Omron CX-Programmer project NewProject (CX-Programmer 2.1)

# PLC NewPLC1: CQM1H CPU51

## Global symbols (name address type ; comment)
PollEnded 200.01 BOOL
PollStatic1 TIM004 BOOL
PollStatic2 TIM005 BOOL
RcvdCmplt 202.00 BOOL
RcvdDrpd 202.01 BOOL
T4_T5Trpd 202.04 BOOL
Tim4_5Chgd 202.02 BOOL

## Program NewProgram1 (no task)
Local symbols
AprchTop 11.00 BOOL
BotSlwDn 0.09 BOOL
BrakeProb1 80.01 BOOL
BrakeProb2 80.02 BOOL
BrkPrRlseTim TIM021 BOOL
BrkSetPB 1.04 BOOL
ByPassON 0.03 BOOL
CarBrake 52.00 BOOL
CarBrkSnsr 52.00 BOOL
Ch3EqlErr 17.00 BOOL
Ch3RngErr 17.01 BOOL
Ch3SnsrlErr 17.00 BOOL  ; Channel 3 is showing a sensor error. Check connections from the temperature module to the thermocouple and also check the thermistor on the module.
Ch60Chgd 70.03 BOOL
Ch60Chgd_ 70.04 BOOL
ChkCarBrkSet TIM151 BOOL
CoolFanMtrOL 1.07 BOOL
CoolFanONDly TIM153 BOOL
DiagDtctd 82.00 BOOL  ; Diagnostic condition has been detected
DiagLtchRst TIM171 BOOL
DiagReset 49.07 BOOL
DiagRstDlay TIM170 BOOL
DnLever 1.03 BOOL
DrmBrkSol 100.02 BOOL
Drum120RPM 0.14 BOOL
DrumDn 1.05 BOOL
DrumMaxSpd TIM159 BOOL
DrumNotDN TIM161 BOOL
DrumNotUP TIM160 BOOL
DrumOvr130RPM 80.06 BOOL
DrumOvrRPM 80.08 BOOL
DrumOvrSpd 0.15 BOOL
DrumOvrSpdTmr TIM157 BOOL
DrumUP 1.06 BOOL
DrumWrongDir 80.09 BOOL
DrvDNPot1 101.02 BOOL
DrvDNPot2 101.03 BOOL
DrvDnCmd1 102.02 BOOL
DrvDnCmd2 102.03 BOOL
DrvUPCmd 102.00 BOOL
DrvUPCmd1 102.00 BOOL
DrvUPCmd2 102.01 BOOL
DrvUPPot1 101.00 BOOL
DrvUPPot2 101.01 BOOL
DwnCntl 99.01 BOOL
EncdrFailBit 80.07 BOOL
EncdrFailTim TIM158 BOOL
FanMtrOL 80.03 BOOL
FloatSw 0.12 BOOL
Flr01Set 11.01 BOOL
Flr02Set 11.02 BOOL
Flr03Set 11.03 BOOL
Flr04Set 11.04 BOOL
Flr05Set 11.05 BOOL
Flr06Set 11.06 BOOL
Flr07Set 11.07 BOOL
Flr08Set 11.08 BOOL
Flr09Set 11.09 BOOL
Flr10Set 11.10 BOOL
Flr11Set 11.11 BOOL
Flr12Set 11.12 BOOL
Flr13Set 11.13 BOOL
Flr14Set 12.01 BOOL
Flr15Set 12.02 BOOL
Flr16Set 12.03 BOOL
Flr17Set 12.04 BOOL
Flr18Set 12.05 BOOL
Flr19Set 12.06 BOOL
Flr20Set 12.07 BOOL
Flr21Set 12.08 BOOL
Flr22Set 12.09 BOOL
Flr23Set 12.10 BOOL
Flr24Set 12.11 BOOL
Flr25Set 12.12 BOOL
Flr26Set 12.13 BOOL
Flr27Set 13.01 BOOL
Flr28Set 13.02 BOOL
Flr29Set 13.03 BOOL
Flr30Set 13.04 BOOL
Flr31Set 13.05 BOOL
Flr32Set 13.06 BOOL
Flr33Set 13.07 BOOL
Flr34Set 13.08 BOOL
Flr356Set 13.10 BOOL
Flr35Set 13.09 BOOL
Flr36Set 13.10 BOOL
Flr37Set 13.11 BOOL
Flr38Set 13.12 BOOL
Flr39Set 13.13 BOOL
Flr40Set 14.01 BOOL
Flr41Set 14.02 BOOL
Flr42Set 14.03 BOOL
Flr43Set 14.04 BOOL
Flr44Set 14.05 BOOL
Flr45Set 14.06 BOOL
Flr46Set 14.07 BOOL
Flr47Set 14.08 BOOL
Flr48Set 14.09 BOOL
Flr49Set 14.10 BOOL
Flr50Set 14.11 BOOL
HiSpLkOut 0.13 BOOL
LdngGates 0.11 BOOL
MainAux 0.00 BOOL
PauseWrite 70.00 BOOL
PollRqst 200.00 BOOL
Prep2Txmt 70.05 BOOL
ResitorA 101.04 BOOL
ResitorB 101.06 BOOL
SSSFault 0.02 BOOL
SSSFaulttMR TIM154 BOOL
SSSNoStart 0.03 BOOL
SafetyLS 52.03 BOOL
SafetyTripped 80.00 BOOL
SafetyTrpd TIM150 BOOL
SetCarBrk 60.00 BOOL
SlkRopeDet 0.10 BOOL
SlowDnCmd 99.03 BOOL
SlowUpCmd 99.02 BOOL
StopMotor 100.01 BOOL
StrUPDly TIM021 BOOL  ; Delays starting the drum in the UP direction until after the drum brake has been released.
StrtDNDly TIM022 BOOL
StrtMotor 100.00 BOOL
StrtWiper 101.05 BOOL
TopSlwDn 0.08 BOOL
TurnFanON 17.03 BOOL
UPCntl 99.00 BOOL
UpLever 1.02 BOOL
VacSetP1 TIM010 BOOL
VacSetP2 TIM011 BOOL
VacShutDN 80.10 BOOL  ; This bit is latched if the vacumm across the oil filter rises too HI
VacShutOFFBit 19.01 BOOL  ; Shutdown the entire machine.
VacTOOHi 19.00 BOOL  ; Change Filter at this point
VacTOOHiBit 19.01 BOOL
ValveShnt 102.04 BOOL
ValveShnt2 102.04 BOOL

### Section Section1

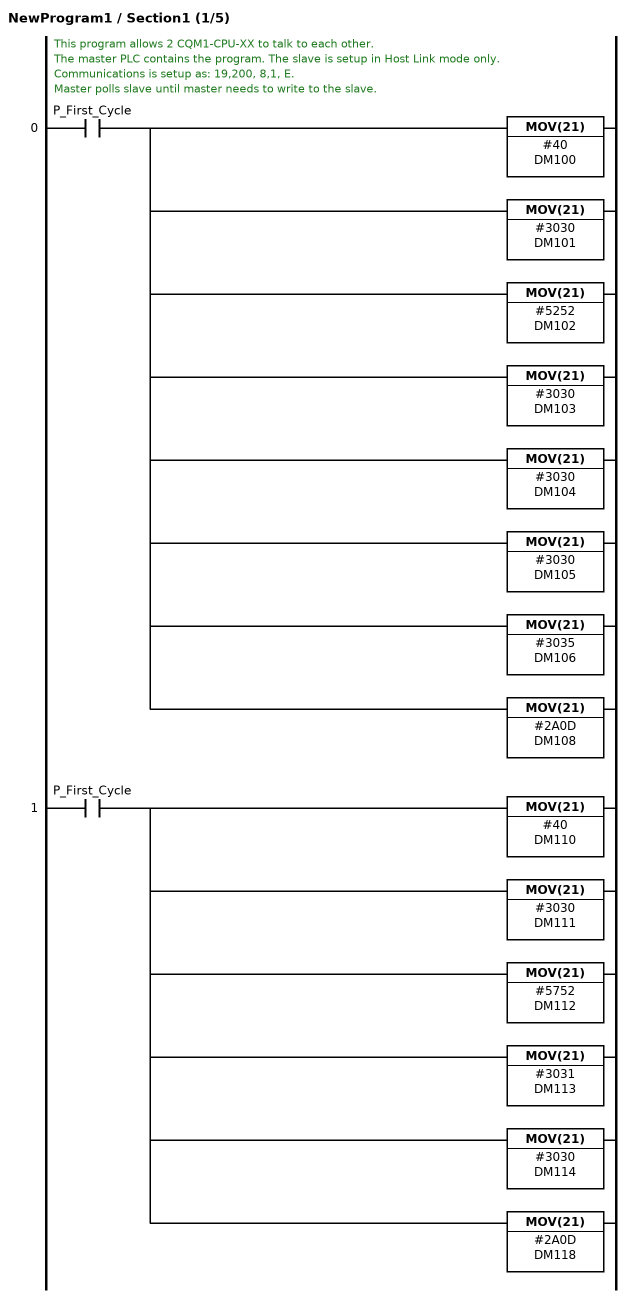
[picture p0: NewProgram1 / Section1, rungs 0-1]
; rung 0: This program allows 2 CQM1-CPU-XX to talk to each other. / The master PLC contains the program. The slave is setup in Host Link mode only. / Communications is setup as: 19,200, 8,1, E. / Master polls slave until master needs to write to the slave.
LD P_First_Cycle
MOV(21) #40 DM100
MOV(21) #3030 DM101
MOV(21) #5252 DM102
MOV(21) #3030 DM103
MOV(21) #3030 DM104
MOV(21) #3030 DM105
MOV(21) #3035 DM106
MOV(21) #2A0D DM108
; rung 1
LD P_First_Cycle
MOV(21) #40 DM110
MOV(21) #3030 DM111
MOV(21) #5752 DM112
MOV(21) #3031 DM113
MOV(21) #3030 DM114
MOV(21) #2A0D DM118

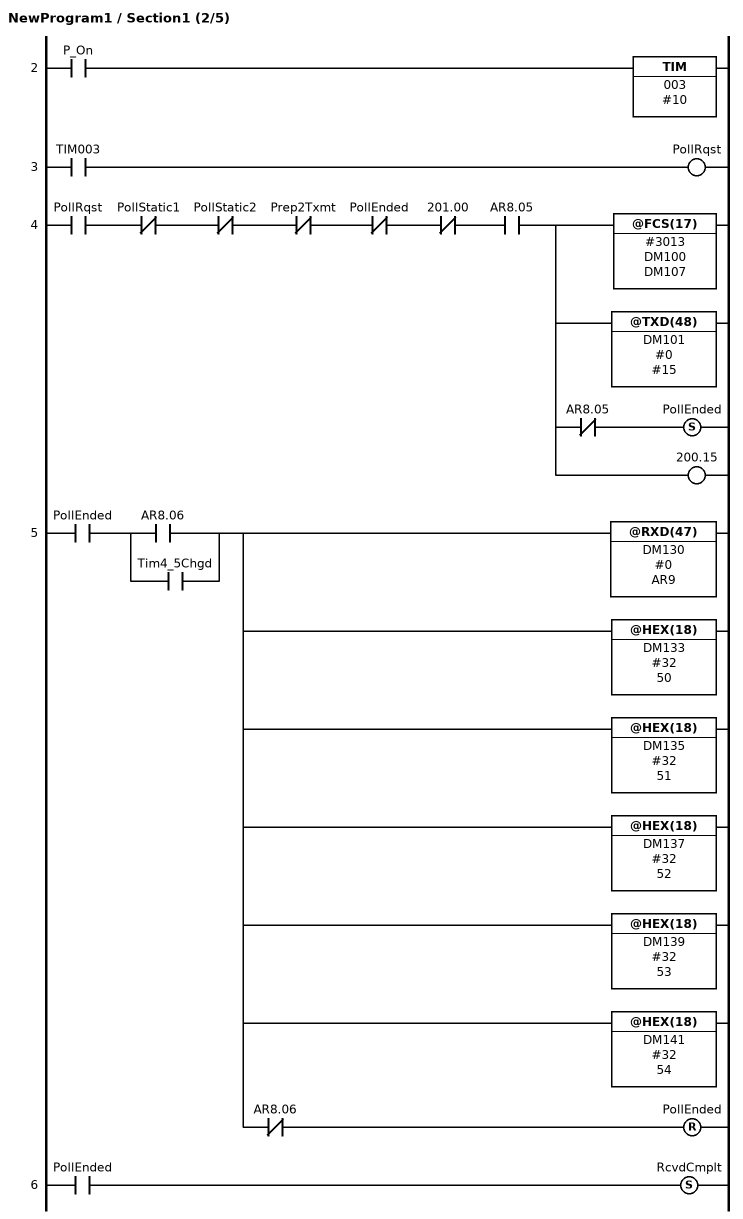
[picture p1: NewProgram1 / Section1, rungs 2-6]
; rung 2
LD P_On
TIM 003 #10
; rung 3
LD TIM003
OUT PollRqst
; rung 4
LD PollRqst
ANDNOT PollStatic1
ANDNOT PollStatic2
ANDNOT Prep2Txmt
ANDNOT PollEnded
ANDNOT 201.00
AND AR8.05
OUT TR0
@FCS(17) #3013 DM100 DM107
@TXD(48) DM101 #0 #15
ANDNOT AR8.05
SET PollEnded
LD TR0
OUT 200.15
; rung 5
LD PollEnded
LD AR8.06
OR Tim4_5Chgd
ANDLD
@RXD(47) DM130 #0 AR9
@HEX(18) DM133 #32 50
@HEX(18) DM135 #32 51
@HEX(18) DM137 #32 52
@HEX(18) DM139 #32 53
@HEX(18) DM141 #32 54
ANDNOT AR8.06
RSET PollEnded
; rung 6
LD PollEnded
SET RcvdCmplt

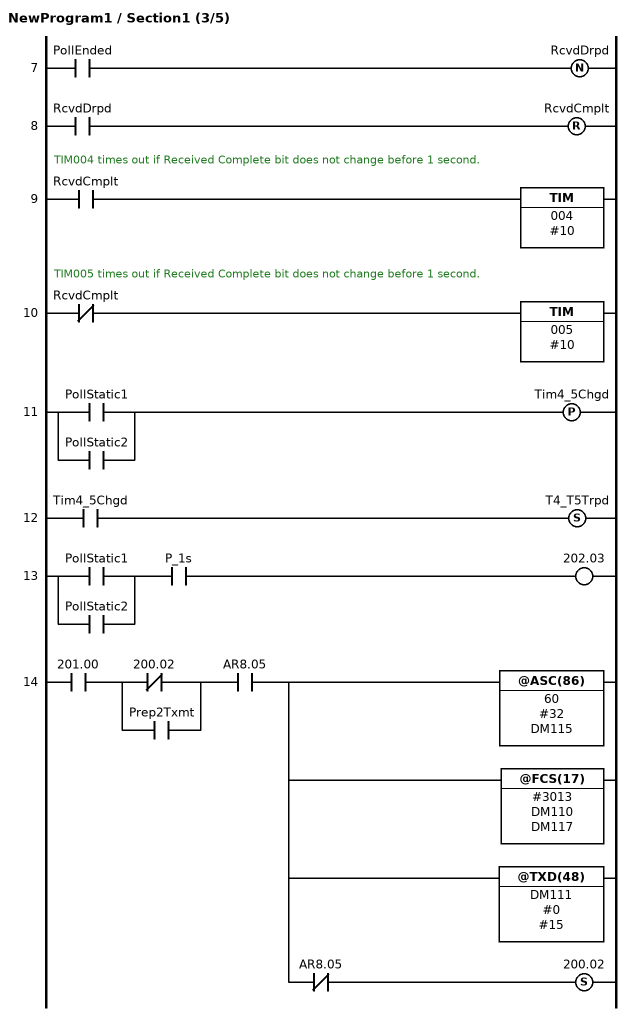
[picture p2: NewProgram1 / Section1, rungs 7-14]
; rung 7
LD PollEnded
DIFD(14) RcvdDrpd
; rung 8
LD RcvdDrpd
RSET RcvdCmplt
; rung 9: TIM004 times out if Received Complete bit does not change before 1 second.
LD RcvdCmplt
TIM 004 #10
; rung 10: TIM005 times out if Received Complete bit does not change before 1 second.
LDNOT RcvdCmplt
TIM 005 #10
; rung 11
LD PollStatic1
OR PollStatic2
DIFU(13) Tim4_5Chgd
; rung 12
LD Tim4_5Chgd
SET T4_T5Trpd
; rung 13
LD PollStatic1
OR PollStatic2
AND P_1s
OUT 202.03
; rung 14
LD 201.00
LDNOT 200.02
OR Prep2Txmt
ANDLD
AND AR8.05
@ASC(86) 60 #32 DM115
@FCS(17) #3013 DM110 DM117
@TXD(48) DM111 #0 #15
ANDNOT AR8.05
SET 200.02

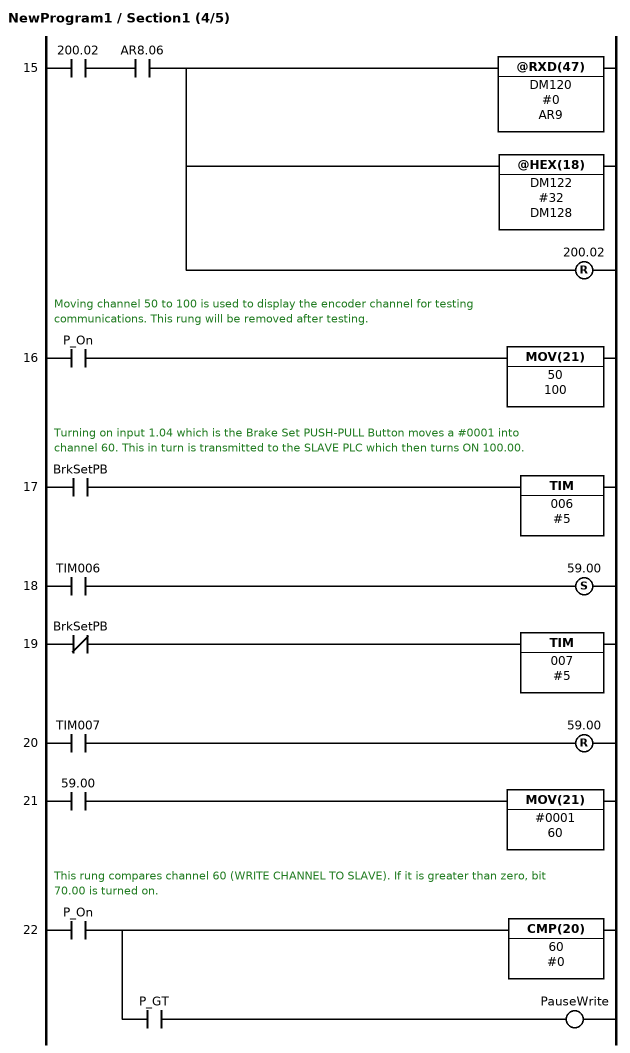
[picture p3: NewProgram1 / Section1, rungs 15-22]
; rung 15
LD 200.02
AND AR8.06
@RXD(47) DM120 #0 AR9
@HEX(18) DM122 #32 DM128
RSET 200.02
; rung 16: Moving channel 50 to 100 is used to display the encoder channel for testing communications. This rung will be removed after testing.
LD P_On
MOV(21) 50 100
; rung 17: Turning on input 1.04 which is the Brake Set PUSH-PULL Button moves a #0001 into channel 60. This in turn is transmitted to the SLAVE PLC which then turns ON 100.00.
LD BrkSetPB
TIM 006 #5
; rung 18
LD TIM006
SET 59.00
; rung 19
LDNOT BrkSetPB
TIM 007 #5
; rung 20
LD TIM007
RSET 59.00
; rung 21
LD 59.00
MOV(21) #0001 60
; rung 22: This rung compares channel 60 (WRITE CHANNEL TO SLAVE). If it is greater than zero, bit 70.00 is turned on.
LD P_On
CMP(20) 60 #0
AND P_GT
OUT PauseWrite

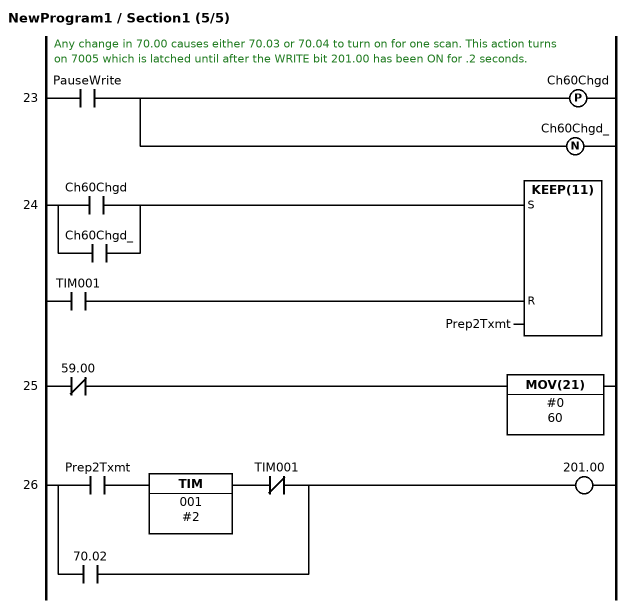
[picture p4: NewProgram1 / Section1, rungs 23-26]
; rung 23: Any change in 70.00 causes either 70.03 or 70.04 to turn on for one scan. This action turns on 7005 which is latched until after the WRITE bit 201.00 has been ON for .2 seconds.
LD PauseWrite
DIFU(13) Ch60Chgd
DIFD(14) Ch60Chgd_
; rung 24
LD Ch60Chgd
OR Ch60Chgd_
LD TIM001
KEEP(11) Prep2Txmt
; rung 25
LDNOT 59.00
MOV(21) #0 60
; rung 26
LD Prep2Txmt
TIM 001 #2
ANDNOT TIM001
OR 70.02
OUT 201.00
; rung 27
END(01)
